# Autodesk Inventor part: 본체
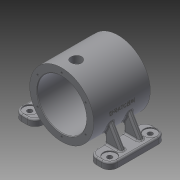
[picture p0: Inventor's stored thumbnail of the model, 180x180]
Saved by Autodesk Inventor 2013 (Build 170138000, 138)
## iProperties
Created: 2024-02
Part Number: 본체
Material: 일반
Document SubType Name: Modeling
Designer: mdu-01
Density: 1 g/cm^3
Author: mdu-01
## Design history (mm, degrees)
sketch "스케치1"
  geometry: C1 r 12 at (0, 11) reference; C2 r 60 at (0, 11); C3 r 46 at (0, 11); C4 r 14 at (0, -20) reference; A1 r 16 centre (0, -20) between (-3.969, -4.5) and (3.969, -4.5) reference; 1 further point
  constraints: 2 centre point, 2 coincident
  dimensions: "d0" = 120 diameter of C2; "d1" = 14 radial gap between concentric circles of C2 C3
extrude "돌출1" new body sketch "스케치1" distance "d2" = 106; taper "d3" = 0 deg
sketch "스케치2"
  geometry: L1 (58, 89)-(67, 89) reference; L2 (71, 0)-(71, 106) reference; L3 (53, 94)-(53, 64) reference; L4 (53, 79)-(71, 79); L5 (67, 89)-(71, 89); L6 (53, 94)-(58, 94); L7 (58, 94)-(58, 89); L8 (53, 79)-(43, 79); L9 (43, 79)-(43, 94); L10 (43, 94)-(53, 94); 1 further point
  constraints: 16 end point, 4 perpendicular, 2 parallel, 2 point on line, 1 horizontal, 1 midpoint, 1 vertical, 2 other
  dimensions: "d5" = 10 distance between parallel lines of L9 L3
revolve "회전1" sketch "스케치2" stored, may be unused: angle "d4" = 90 deg
sketch "스케치3"
  geometry: C1 r 60 at (0, 0) reference; 2 further points
  constraints: 2 vertical alignment, 2 other
  dimensions: "d6" = 8 dimension on C1
hole "구멍1" sketch "스케치3" at (0, 52) diameter "d7" = 3.242; stored, may be unused: countersink angle "d11" = 90 deg, drill point angle "d13" = 118 deg; dims "d8" = 8, "d9" = 8, "d10" = 4.6, "d12" = 10
hole "구멍2" diameter "d16" = 3.242; stored, may be unused: countersink angle "d20" = 90 deg, drill point angle "d22" = 118 deg; dims "d14" = 10, "d15" = 10, "d17" = 8, "d18" = 8, "d19" = 4.6, "d21" = 10
sketch "스케치4"
  geometry: L1 (50, -54)-(90, -54); L2 (90, -54)-(90, -42); L3 (90, -42)-(50, -42); L4 (50, -42)-(50, -54); C1 r 60 at (0, 11) reference; 1 further point
  constraints: 8 end point, 2 parallel, 1 horizontal, 1 perpendicular
  dimensions: "d26" = 12 distance between parallel lines of L1 L3; "d28" = 65 distance from line of L1 C1.centre; "d29" = 50 distance from line of L4 C1.centre; "d30" = 40 distance between parallel lines of L2 L4
extrude "돌출2" join sketch "스케치4" distance "d31" = 106; taper "d32" = 0 deg
node "작업 평면1"
sketch "스케치5"
  geometry: L1 (-90, -42)-(-50, -42) reference; L2 (-50, -42)-(-50, -22.166); L3 (-80, -42)-(-58.084, -4.041); A1 r 60 centre (0, 11) between (-50, -22.166) and (-58.084, -4.041) reference; 1 further point
  constraints: 4 end point, 2 point on circle, 1 perpendicular, 1 point on line
  dimensions: "d33" = 10 distance of L3.start L1.start; "d34" = 60 deg angle of L1 L3
extrude "돌출3" join sketch "스케치5" distance "d37" = 9; taper "d38" = 0 deg
node "작업 평면3"
fillet "모깎기1" dims "d39" = 15
sketch "스케치6"
  geometry: A1 r 15 centre (25, 16) between (40, 16) and (25, 31) reference; A2 r 15 centre (25, -60) between (25, -75) and (40, -60) reference; 1 further point
hole "구멍3" sketch "스케치6" at (25, -60), (25, 16) diameter "d40" = 9; stored, may be unused: countersink angle "d44" = 90 deg, drill point angle "d46" = 118 deg; dims "d41" = 8, "d42" = 24, "d43" = 2, "d45" = 10
fillet "모깎기2" dims "d47" = 3
fillet "모깎기3" dims "d48" = 3
fillet "모깎기4" dims "d49" = 3
fillet "모깎기5" dims "d50" = 3
sketch "스케치7"
  geometry: L1 (71, 106)-(-49, 106) reference; 3 further points
  constraints: 1 midpoint, 1 vertical alignment, 1 other
  dimensions: "d51" = 53 distance from line of point (11, 53) L1
feature "엠보싱1" sketch "스케치7" dims "d0" = 120, "d1" = 14, "d52" = 0.5, "d53" = 0
chamfer "모따기1" distance "d54" = 1; stored, may be unused: second distance "d55" = 2, angle "d56" = 45 deg
node "솔리드1"
pattern_circular "원형 패턴1" dims angle "d24" = 360 deg
mirror "대칭1"
mirror "대칭2"
node "참조1"
node "참조2"
node "참조3"
node "참조4"
